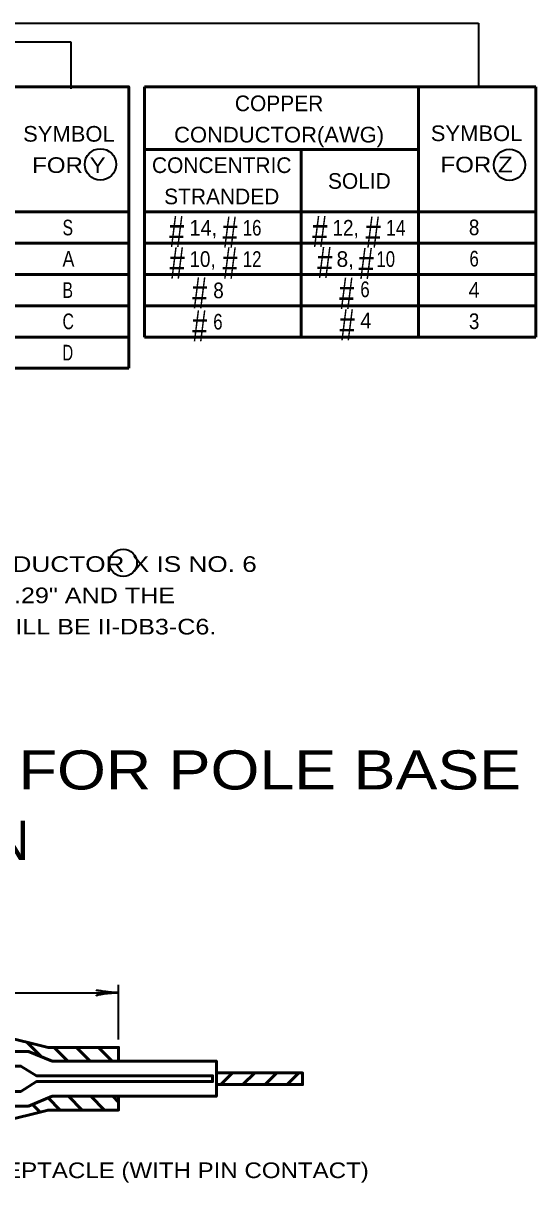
# Model space of a CAD drawing. Extents: x -1 to 679, y 0 to 440.
# Drawn here: x 367.7 to 433.2, y 153.2 to 301.5 of the extents above; entities that cross this region are included whole.
import ezdxf
from ezdxf.enums import TextEntityAlignment as Align

# ---------------------------------------------------------------- set-up
doc = ezdxf.new("R2010")
doc.units = 0
doc.header["$LTSCALE"] = 0.8
doc.layers.add('1', color=7, linetype='Continuous', lineweight=53)

msp = doc.modelspace()

# ---------------------------------------------------------------- linework, layer by layer
at = {"layer": '1', "lineweight": 35}
for p, q in [((337.4045, 301.5149), (425.9044, 301.5149)), ((425.9044, 301.5149), (425.9044, 293.5149)), ((330.8241, 299.1399), (373.7847, 299.1399)), ((373.7847, 299.1399), (373.7847, 293.1399)), ((379.8991, 171.5513), (379.8991, 178.5513)), ((312.8991, 177.5513), (379.8991, 177.5513))]:
    msp.add_line(p, q, dxfattribs=at)
at = {"layer": '1'}
for p, q in [((383.2067, 293.3847), (383.2067, 261.3847)), ((383.2067, 293.3847), (433.2067, 293.3847)), ((418.2067, 293.3847), (418.2067, 261.3847)), ((433.2067, 293.3847), (433.2067, 261.3847)), ((383.2067, 285.3847), (418.2067, 285.3847)), ((403.2067, 285.3847), (403.2067, 261.3847)), ((336.2067, 277.3847), (381.2067, 277.3847)), ((383.2067, 277.3847), (433.2067, 277.3847)), ((336.2067, 273.3847), (381.2067, 273.3847)), ((383.2067, 273.3847), (433.2067, 273.3847)), ((336.2067, 269.3847), (381.2067, 269.3847)), ((383.2067, 269.3847), (433.2067, 269.3847)), ((336.2067, 265.3847), (381.2067, 265.3847)), ((383.2067, 265.3847), (433.2067, 265.3847)), ((336.2067, 261.3847), (381.2067, 261.3847)), ((383.2067, 261.3847), (433.2067, 261.3847)), ((336.2067, 257.3847), (381.2067, 257.3847)), ((370.0249, 169.3739), (368.1636, 171.2352)), ((373.4259, 168.8013), (371.6759, 170.5513)), ((376.2543, 168.8013), (374.5043, 170.5513)), ((379.0827, 168.8013), (377.3327, 170.5513)), ((392.9608, 165.8013), (394.4608, 167.3013)), ((395.7892, 165.8013), (397.2892, 167.3013)), ((398.6177, 165.8013), (400.1177, 167.3013)), ((401.4461, 165.8013), (402.9461, 167.3013)), ((369.8585, 162.2912), (368.8927, 163.257)), ((372.4268, 162.5513), (370.8893, 164.0889)), ((375.2552, 162.5513), (373.5052, 164.3013)), ((378.0837, 162.5513), (376.3337, 164.3013)), ((379.8991, 163.5643), (379.1621, 164.3013))]:
    msp.add_line(p, q, dxfattribs=at)
for points in [[(336.2067, 293.3847), (381.2067, 293.3847), (381.2067, 257.3847)], [(379.8991, 168.8013), (379.8991, 170.5513), (370.8991, 170.5513), (364.8991, 172.0513), (364.8991, 173.0513), (341.8991, 173.0513), (341.8991, 171.0513), (351.8991, 171.0513), (351.8991, 167.9263)], [(356.3991, 168.1763), (357.3991, 170.0513), (368.3991, 170.0513), (371.3991, 168.8013), (392.3991, 168.8013), (379.8991, 168.8013)], [(392.3991, 164.3013), (392.3991, 168.8013), (392.3991, 167.3013)], [(392.3991, 167.3013), (403.3991, 167.3013), (403.3991, 165.8013), (392.3991, 165.8013)], [(379.8991, 164.3013), (379.8991, 162.5513), (370.8991, 162.5513), (364.8991, 161.0513), (364.8991, 160.0513), (341.8991, 160.0513), (341.8991, 162.0513), (351.8991, 162.0513), (351.8991, 165.1763)], [(356.3991, 164.9263), (357.3991, 163.0513), (368.3991, 163.0513), (371.3991, 164.3013), (392.3991, 164.3013), (379.8991, 164.3013)]]:
    msp.add_lwpolyline(points, dxfattribs=at)
msp.add_lwpolyline([(356.3991, 168.1763), (357.3991, 170.0513), (368.3991, 170.0513), (371.3991, 168.8013), (392.3991, 168.8013), (392.3991, 164.3013), (371.3991, 164.3013), (368.3991, 163.0513), (357.3991, 163.0513), (356.3991, 164.9263), (367.3991, 164.9263), (369.3991, 166.1763), (391.8991, 166.1763), (391.8991, 166.9263), (369.3991, 166.9263), (367.3991, 168.1763)], close=True, dxfattribs=at)
at = {"layer": '1', "lineweight": 35}
for centre, radius in [((377.5777, 283.4635), 2), ((429.8446, 283.3997), 2), ((380.4993, 232.5219), 1.75)]:
    msp.add_circle(centre, radius, dxfattribs=at)
at = {"layer": '1', "lineweight": 40}
for centre, major_axis, ratio, start_param, end_param in [((378.7786, 177.7629), (1.7565, -0.1757), 0.07063, 3.14071475, 5.41810995), ((378.8079, 177.275), (1.7857, 0.1562), 0.122415, 0.89635335, 3.14159265)]:
    msp.add_ellipse(centre, major_axis=major_axis, ratio=ratio, start_param=start_param, end_param=end_param, dxfattribs=at)

# ---------------------------------------------------------------- texts
at = {"layer": '1'}
for s, p in [('COPPER', (400.406, 290.2639)), ('CONCENTRIC', (393.0781, 282.36)), ('STRANDED', (393.078, 278.36))]:
    msp.add_text(s, height=2, dxfattribs=at).set_placement(p, align=Align.CENTER)
for s, height, width, p in [('SYMBOL', 2, 1.05, (373.5531, 286.3677)), ('CONDUCTOR(AWG)', 2, 1.05, (400.406, 286.2639)), ('SYMBOL', 2, 1.05, (425.639, 286.4394)), ('FOR Y', 2, 1.15, (373.553, 282.3677)), ('FOR Z', 2, 1.15, (425.639, 282.4394)), ('8', 2, 0.9, (425.3288, 274.4078)), ('6', 2, 0.8, (425.3288, 270.4078)), ('4', 2, 0.95, (425.3287, 266.4078)), ('3', 2, 0.9, (425.3288, 262.4078)), ('FUSED "Y" CONNECTOR KIT FOR POLE BASE', 5, 1.2, (343.5636, 203.536)), ('INSTALLATION', 5, 1.05, (343.5636, 194.536))]:
    msp.add_text(s, height=height, dxfattribs=dict(at, width=width)).set_placement(p, align=Align.CENTER)
for s, p in [('SOLID', (406.6505, 280.3402)), ('8,', (407.7476, 270.3576))]:
    msp.add_text(s, height=2, dxfattribs=at).set_placement(p)
for s, height, width, p in [('S', 2, 0.75, (372.7372, 274.3908)), ('#', 4, 0.65, (386.3581, 272.8778)), ('14,', 2, 0.95, (388.9559, 274.3576)), ('#', 4, 0.65, (393.174, 272.8141)), ('16', 2, 0.8, (395.7718, 274.3576)), ('#', 4, 0.65, (404.6401, 272.8778)), ('12,', 2, 0.9, (407.2379, 274.3576)), ('#', 4, 0.65, (411.456, 272.8141)), ('14', 2, 0.85, (414.0538, 274.3576)), ('#', 4, 0.65, (386.4218, 268.8634)), ('#', 4, 0.65, (393.174, 268.8633)), ('#', 4, 0.65, (405.2771, 268.9272)), ('A', 2, 0.85, (372.7372, 270.3908)), ('10,', 2, 0.9, (388.9559, 270.3576)), ('12', 2, 0.8, (395.7718, 270.3576)), ('#', 4, 0.65, (410.5642, 268.7997)), ('10', 2, 0.8, (412.8435, 270.3575)), ('B', 2, 0.75, (372.7372, 266.3908)), ('#', 4, 0.65, (389.2883, 265.0401)), ('8', 2, 0.9, (391.9962, 266.3459)), ('#', 4, 0.65, (408.0798, 264.9802)), ('6', 2, 0.8, (410.7878, 266.4878)), ('C', 2, 0.75, (372.7372, 262.3908)), ('#', 4, 0.65, (389.2883, 260.8383)), ('6', 2, 0.8, (391.9962, 262.3459)), ('#', 4, 0.65, (408.1416, 260.9638)), ('4', 2, 0.95, (410.7878, 262.4878)), ('D', 2, 0.7, (372.7372, 258.3908)), ('IF THE LINE OUTSIDE DIAMETER W IS .42" AND THE CONDUCTOR X IS NO. 6', 2, 1.25, (274.5172, 231.3548)), ('STRANDED, AND THE LOAD SIDE OUTSIDE DIAMETER Y IS .29" AND THE', 2, 1.2, (274.5172, 227.3548)), ('CONDUCTOR Z IS NO. 12 STRANDED THE KIT REQUIRED WILL BE II-DB3-C6.', 2, 1.2, (274.5172, 223.3548)), ('RECEPTACLE (WITH PIN CONTACT)', 2, 1.15, (358.8988, 153.8458))]:
    msp.add_text(s, height=height, dxfattribs=dict(at, width=width)).set_placement(p)

doc.saveas('drawing.dxf')
